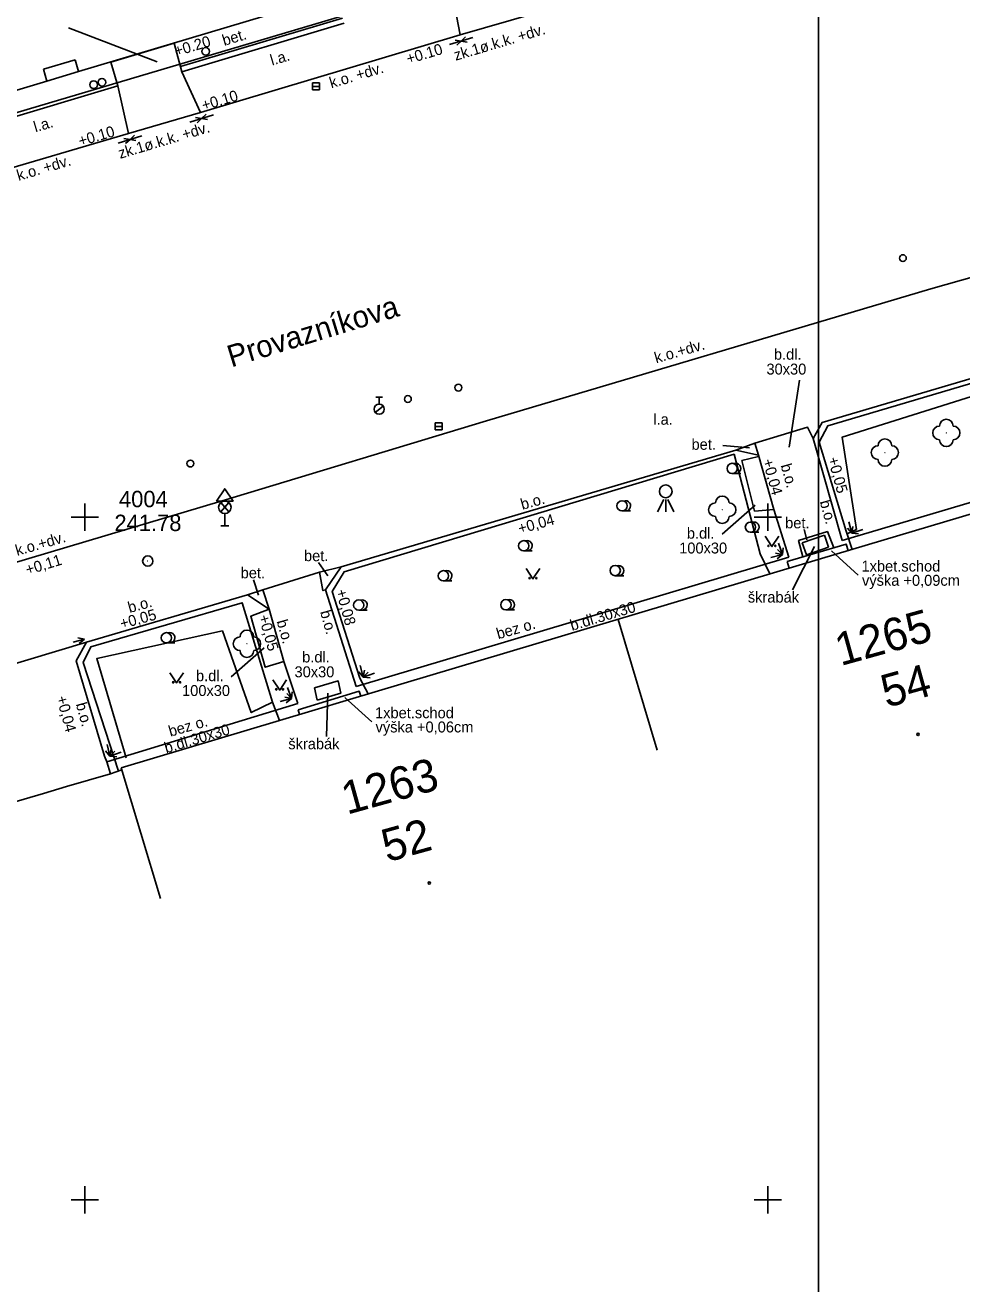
# Model space of a CAD drawing. Extents: x -597333 to -596488, y -1158921 to -1158644.
# Drawn here: x -596727.19 to -596692.9, y -1158753.07 to -1158706.99 of the extents above; entities that cross this region are included whole.
import ezdxf

# ---------------------------------------------------------------- set-up
doc = ezdxf.new("R2010")
doc.units = 0
for name, color, linetype in [('Vrstva 1', 7, 'Continuous'), ('Vrstva 11', 7, 'Continuous'), ('Vrstva 12', 7, 'Continuous'), ('Vrstva 14', 7, 'Continuous'), ('Vrstva 15', 7, 'Continuous'), ('Vrstva 2', 7, 'Continuous'), ('Vrstva 24', 7, 'Continuous'), ('Vrstva 25', 7, 'Continuous'), ('Vrstva 4', 7, 'Continuous'), ('Vrstva 42', 7, 'Continuous'), ('Vrstva 43', 7, 'Continuous'), ('Vrstva 44', 7, 'Continuous'), ('Vrstva 49', 7, 'Continuous'), ('Vrstva 5', 7, 'Continuous'), ('Vrstva 50', 7, 'Continuous'), ('Vrstva 62', 7, 'Continuous'), ('Vrstva 7', 7, 'Continuous'), ('Vrstva 9', 7, 'Continuous')]:
    doc.layers.add(name, color=color, linetype=linetype)

msp = doc.modelspace()

# ---------------------------------------------------------------- linework, layer by layer
at = {"layer": 'Vrstva 1'}
msp.add_lwpolyline([(-596908.148, -1158651.282), (-596908.148, -1158799.157), (-596698.148, -1158799.157), (-596698.148, -1158650.657), (-596905.25, -1158650.657)], dxfattribs=at)
msp.add_lwpolyline([(-596698.148, -1158650.657), (-596698.148, -1158799.157), (-596488.148, -1158799.157), (-596488.148, -1158650.657)], close=True, dxfattribs=at)
at = {"layer": 'Vrstva 11'}
for points in [[(-596684.09, -1158717.92), (-596697.28, -1158722.07), (-596696.76, -1158725.45), (-596697.07, -1158725.6)], [(-596718.13, -1158731.78), (-596718.91, -1158732.16), (-596719.97, -1158729.17), (-596724.57, -1158730.18), (-596723.49, -1158733.81)]]:
    msp.add_lwpolyline(points, dxfattribs=at)
at = {"layer": 'Vrstva 12'}
for p, q in [((-596724.07, -1158734.4), (-596723.65, -1158734.25)), ((-596726.52, -1158735.12), (-596725.68, -1158734.86))]:
    msp.add_line(p, q, dxfattribs=at)
at = {"layer": 'Vrstva 14'}
for p, q in [((-596701.31, -1158723.408), (-596700.998, -1158723.408)), ((-596705.34, -1158724.778), (-596705.027, -1158724.778)), ((-596700.64, -1158725.558), (-596700.328, -1158725.558)), ((-596708.94, -1158726.238), (-596708.628, -1158726.238)), ((-596711.88, -1158727.338), (-596711.568, -1158727.338)), ((-596705.59, -1158727.148), (-596705.277, -1158727.148)), ((-596714.98, -1158728.408), (-596714.667, -1158728.408)), ((-596709.59, -1158728.398), (-596709.277, -1158728.398)), ((-596722.02, -1158729.608), (-596721.708, -1158729.608))]:
    msp.add_line(p, q, dxfattribs=at)
for points in [[(-596700.104, -1158725.704), (-596699.854, -1158726.079), (-596699.604, -1158725.704)], [(-596708.85, -1158726.887), (-596708.6, -1158727.262), (-596708.35, -1158726.887)], [(-596721.894, -1158730.7), (-596721.644, -1158731.075), (-596721.394, -1158730.7)], [(-596718.122, -1158730.958), (-596717.872, -1158731.333), (-596717.622, -1158730.958)]]:
    msp.add_lwpolyline(points, dxfattribs=at)
for centre, radius in [((-596693.47, -1158721.92), 0.00025), ((-596695.72, -1158722.64), 0.00025), ((-596701.31, -1158723.22), 0.188), ((-596705.34, -1158724.59), 0.188), ((-596701.67, -1158724.73), 0.00025), ((-596700.64, -1158725.37), 0.188), ((-596708.94, -1158726.05), 0.188), ((-596699.979, -1158726.054), 0.025), ((-596699.729, -1158726.054), 0.025), ((-596705.59, -1158726.96), 0.188), ((-596711.88, -1158727.15), 0.188), ((-596708.725, -1158727.237), 0.025), ((-596708.475, -1158727.237), 0.025), ((-596714.98, -1158728.22), 0.188), ((-596709.59, -1158728.21), 0.188), ((-596722.02, -1158729.42), 0.188), ((-596719.07, -1158729.64), 0.00025), ((-596721.769, -1158731.05), 0.025), ((-596721.519, -1158731.05), 0.025), ((-596717.997, -1158731.308), 0.025), ((-596717.747, -1158731.308), 0.025)]:
    msp.add_circle(centre, radius, dxfattribs=at)
for centre, radius, start, end in [((-596693.72, -1158721.92), 0.25, 90, 270), ((-596693.47, -1158721.67), 0.25, 0, 180), ((-596693.22, -1158721.92), 0.25, 270, 90), ((-596695.72, -1158722.39), 0.25, 0, 180), ((-596693.47, -1158722.17), 0.25, 180, 360), ((-596695.97, -1158722.64), 0.25, 90, 270), ((-596695.47, -1158722.64), 0.25, 270, 90), ((-596701.185, -1158723.22), 0.188, 249.4944, 109.0474), ((-596695.72, -1158722.89), 0.25, 180, 360), ((-596705.215, -1158724.59), 0.188, 249.4944, 109.0474), ((-596701.92, -1158724.73), 0.25, 90, 270), ((-596701.67, -1158724.48), 0.25, 0, 180), ((-596701.42, -1158724.73), 0.25, 270, 90), ((-596701.67, -1158724.98), 0.25, 180, 360), ((-596700.515, -1158725.37), 0.188, 249.4944, 109.0474), ((-596708.815, -1158726.05), 0.188, 249.4944, 109.0474), ((-596705.465, -1158726.96), 0.188, 249.4944, 109.0474), ((-596711.755, -1158727.15), 0.188, 249.4944, 109.0474), ((-596714.855, -1158728.22), 0.188, 249.4944, 109.0474), ((-596709.465, -1158728.21), 0.188, 249.4944, 109.0474), ((-596721.895, -1158729.42), 0.188, 249.4944, 109.0474), ((-596719.07, -1158729.39), 0.25, 0, 180), ((-596719.32, -1158729.64), 0.25, 90, 270), ((-596718.82, -1158729.64), 0.25, 270, 90), ((-596719.07, -1158729.89), 0.25, 180, 360)]:
    msp.add_arc(centre, radius, start, end, dxfattribs=at)
at = {"layer": 'Vrstva 15'}
for centre in [(-596694.506, -1158732.959), (-596712.399, -1158738.402)]:
    msp.add_circle(centre, 0.0438, dxfattribs=at)
at = {"layer": 'Vrstva 2'}
for radius in [0.188, 0.00025]:
    msp.add_circle((-596722.7, -1158726.61), radius, dxfattribs=at)
at = {"layer": 'Vrstva 24'}
for p, q in [((-596714.377, -1158721.166), (-596714.082, -1158720.934)), ((-596714.355, -1158720.613), (-596714.105, -1158720.613)), ((-596714.23, -1158720.863), (-596714.23, -1158720.613))]:
    msp.add_line(p, q, dxfattribs=at)
for centre, radius in [((-596695.06, -1158715.52), 0.125), ((-596711.33, -1158720.26), 0.125), ((-596714.23, -1158721.05), 0.188), ((-596713.18, -1158720.68), 0.125), ((-596721.14, -1158723.04), 0.125)]:
    msp.add_circle(centre, radius, dxfattribs=at)
at = {"layer": 'Vrstva 25'}
for p, q in [((-596716.665, -1158709.23), (-596716.415, -1158709.23)), ((-596712.175, -1158721.68), (-596711.925, -1158721.68))]:
    msp.add_line(p, q, dxfattribs=at)
for points in [[(-596716.665, -1158709.355), (-596716.415, -1158709.355), (-596716.415, -1158709.105), (-596716.665, -1158709.105)], [(-596712.175, -1158721.806), (-596711.925, -1158721.806), (-596711.925, -1158721.555), (-596712.175, -1158721.555)]]:
    msp.add_lwpolyline(points, close=True, dxfattribs=at)
at = {"layer": 'Vrstva 4'}
for p, q in [((-596728.69, -1158710.54), (-596712.35, -1158705.69)), ((-596725.363, -1158708.26), (-596725.235, -1158708.692)), ((-596726.392, -1158709.037), (-596726.52, -1158708.605)), ((-596726.392, -1158709.037), (-596725.235, -1158708.692)), ((-596697.471, -1158726.348), (-596681.356, -1158721.53)), ((-596715.313, -1158731.682), (-596698.853, -1158726.761)), ((-596704.056, -1158733.535), (-596705.488, -1158728.745)), ((-596723.67, -1158734.18), (-596716.695, -1158732.095)), ((-596722.238, -1158738.971), (-596723.67, -1158734.18))]:
    msp.add_line(p, q, dxfattribs=at)
for points in [[(-596725.235, -1158708.692), (-596718.4, -1158706.652)], [(-596732.77, -1158710.94), (-596726.392, -1158709.037)], [(-596697.058, -1158726.224), (-596697.138, -1158725.988), (-596699.298, -1158726.628)], [(-596699.217, -1158726.87), (-596699.298, -1158726.628)], [(-596714.901, -1158731.558), (-596714.96, -1158731.38), (-596717.2, -1158732.06)], [(-596717.144, -1158732.229), (-596717.2, -1158732.06)]]:
    msp.add_lwpolyline(points, dxfattribs=at)
for centre in [(-596720.58, -1158707.95), (-596724.38, -1158709.08), (-596724.68, -1158709.17)]:
    msp.add_circle(centre, 0.14, dxfattribs=at)
at = {"layer": 'Vrstva 44'}
for p, q in [((-596719.73, -1158724.47), (-596720.03, -1158724.814)), ((-596720.03, -1158724.47), (-596719.73, -1158724.814)), ((-596703.814, -1158724.353), (-596704.04, -1158724.805)), ((-596703.74, -1158724.355), (-596703.74, -1158724.805)), ((-596703.665, -1158724.353), (-596703.44, -1158724.805)), ((-596719.88, -1158725.32), (-596719.88, -1158724.87)), ((-596720.03, -1158725.32), (-596719.73, -1158725.32))]:
    msp.add_line(p, q, dxfattribs=at)
msp.add_lwpolyline([(-596720.18, -1158724.414), (-596719.58, -1158724.414), (-596719.88, -1158723.964), (-596720.18, -1158724.414)], dxfattribs=at)
for centre, radius in [((-596703.74, -1158724.06), 0.234), ((-596719.88, -1158724.642), 0.228)]:
    msp.add_circle(centre, radius, dxfattribs=at)
at = {"layer": 'Vrstva 49'}
for p, q in [((-596725.601, -1158707.092), (-596722.361, -1158708.338)), ((-596710.798, -1158707.441), (-596711.66, -1158707.701)), ((-596711.229, -1158707.571), (-596711.449, -1158707.536)), ((-596711.229, -1158707.571), (-596711.393, -1158707.724)), ((-596711.229, -1158707.571), (-596711.067, -1158707.417)), ((-596711.229, -1158707.571), (-596711.011, -1158707.609)), ((-596720.3, -1158710.279), (-596721.162, -1158710.539)), ((-596720.731, -1158710.409), (-596720.569, -1158710.255)), ((-596720.731, -1158710.409), (-596720.951, -1158710.374)), ((-596720.731, -1158710.409), (-596720.895, -1158710.562)), ((-596720.731, -1158710.409), (-596720.513, -1158710.447)), ((-596722.92, -1158711.045), (-596723.782, -1158711.305)), ((-596723.351, -1158711.175), (-596723.571, -1158711.14)), ((-596723.351, -1158711.175), (-596723.515, -1158711.328)), ((-596723.351, -1158711.175), (-596723.189, -1158711.021)), ((-596723.351, -1158711.175), (-596723.133, -1158711.213)), ((-596698.841, -1158719.993), (-596699.229, -1158722.443)), ((-596701.655, -1158722.384), (-596700.669, -1158722.47)), ((-596701.681, -1158725.628), (-596700.473, -1158724.565)), ((-596698.677, -1158725.454), (-596698.572, -1158725.838)), ((-596697.093, -1158725.401), (-596696.935, -1158725.595)), ((-596696.888, -1158725.349), (-596696.935, -1158725.595)), ((-596696.755, -1158725.42), (-596696.935, -1158725.595)), ((-596696.686, -1158725.62), (-596696.935, -1158725.595)), ((-596699.718, -1158726.324), (-596699.473, -1158726.37)), ((-596699.666, -1158726.529), (-596699.473, -1158726.37)), ((-596699.647, -1158726.191), (-596699.473, -1158726.37)), ((-596699.447, -1158726.122), (-596699.473, -1158726.37)), ((-596716.448, -1158726.659), (-596716.106, -1158727.147)), ((-596718.831, -1158727.301), (-596718.647, -1158727.855)), ((-596725.259, -1158729.423), (-596725.014, -1158729.469)), ((-596725.207, -1158729.628), (-596725.014, -1158729.469)), ((-596719.647, -1158730.846), (-596718.44, -1158729.783)), ((-596714.767, -1158730.611), (-596714.814, -1158730.857)), ((-596714.972, -1158730.664), (-596714.814, -1158730.857)), ((-596714.634, -1158730.683), (-596714.814, -1158730.857)), ((-596714.565, -1158730.883), (-596714.814, -1158730.857)), ((-596717.613, -1158731.465), (-596717.439, -1158731.645)), ((-596717.413, -1158731.396), (-596717.439, -1158731.645)), ((-596717.684, -1158731.599), (-596717.439, -1158731.645)), ((-596717.632, -1158731.803), (-596717.439, -1158731.645)), ((-596724.243, -1158733.556), (-596724.085, -1158733.749)), ((-596724.039, -1158733.504), (-596724.085, -1158733.749)), ((-596723.906, -1158733.575), (-596724.085, -1158733.749)), ((-596723.836, -1158733.775), (-596724.085, -1158733.749))]:
    msp.add_line(p, q, dxfattribs=at)
for points in [[(-596697.042, -1158725.174), (-596696.935, -1158725.595)], [(-596696.525, -1158725.452), (-596696.935, -1158725.595)], [(-596699.615, -1158725.96), (-596699.473, -1158726.37)], [(-596699.893, -1158726.478), (-596699.473, -1158726.37)], [(-596698.299, -1158726.08), (-596699.098, -1158727.665)], [(-596697.677, -1158726.24), (-596696.699, -1158727.13)], [(-596725.434, -1158729.577), (-596725.014, -1158729.469)], [(-596714.921, -1158730.436), (-596714.814, -1158730.857)], [(-596714.404, -1158730.715), (-596714.814, -1158730.857)], [(-596717.581, -1158731.235), (-596717.439, -1158731.645)], [(-596716.105, -1158731.451), (-596716.156, -1158733.035)], [(-596717.859, -1158731.752), (-596717.439, -1158731.645)], [(-596715.483, -1158731.611), (-596714.505, -1158732.501)], [(-596724.192, -1158733.329), (-596724.085, -1158733.749)], [(-596723.675, -1158733.607), (-596724.085, -1158733.749)]]:
    msp.add_lwpolyline(points, dxfattribs=at)
at = {"layer": 'Vrstva 5'}
for p, q in [((-596721.737, -1158707.649), (-596724.047, -1158708.339)), ((-596726.52, -1158708.605), (-596725.363, -1158708.26)), ((-596697.14, -1158725.52), (-596696.919, -1158726.183)), ((-596700.29, -1158726.35), (-596699.93, -1158727.083)), ((-596697.471, -1158726.348), (-596698.853, -1158726.761)), ((-596714.629, -1158731.477), (-596714.94, -1158730.9)), ((-596718.13, -1158731.78), (-596717.878, -1158732.448)), ((-596715.313, -1158731.682), (-596716.695, -1158732.095)), ((-596725.68, -1158734.86), (-596724.07, -1158734.4)), ((-596730.15, -1158736.19), (-596726.52, -1158735.12))]:
    msp.add_line(p, q, dxfattribs=at)
at = {"layer": 'Vrstva 62'}
for p, q in [((-596725, -1158724.5), (-596725, -1158725.5)), ((-596700, -1158724.5), (-596700, -1158725.5)), ((-596725.5, -1158725), (-596724.5, -1158725)), ((-596700.5, -1158725), (-596699.5, -1158725)), ((-596725, -1158749.5), (-596725, -1158750.5)), ((-596700, -1158749.5), (-596700, -1158750.5)), ((-596725.5, -1158750), (-596724.5, -1158750)), ((-596700.5, -1158750), (-596699.5, -1158750))]:
    msp.add_line(p, q, dxfattribs=at)
at = {"layer": 'Vrstva 7'}
for p, q in [((-596711.57, -1158705.73), (-596711.27, -1158707.34)), ((-596721.503, -1158708.507), (-596715.567, -1158706.728)), ((-596721.45, -1158708.7), (-596715.51, -1158706.92)), ((-596721.45, -1158708.7), (-596721.737, -1158707.649)), ((-596723.8, -1158709.21), (-596724.047, -1158708.339)), ((-596720.77, -1158710.19), (-596721.45, -1158708.7)), ((-596729.41, -1158710.9), (-596723.8, -1158709.21)), ((-596723.8, -1158709.21), (-596723.4, -1158710.96)), ((-596697.28, -1158725.86), (-596681.932, -1158721.281)), ((-596698.75, -1158725.94), (-596697.93, -1158725.66)), ((-596698.59, -1158726.38), (-596698.75, -1158725.94)), ((-596697.93, -1158725.66), (-596697.78, -1158726.1)), ((-596715.07, -1158731.21), (-596699.24, -1158726.47)), ((-596697.78, -1158726.1), (-596698.59, -1158726.38)), ((-596734.01, -1158732.32), (-596724.94, -1158729.58)), ((-596724.2, -1158733.96), (-596717.21, -1158731.83))]:
    msp.add_line(p, q, dxfattribs=at)
for points in [[(-596731.26, -1158713.3), (-596728.72, -1158712.52), (-596723.4, -1158710.96), (-596720.77, -1158710.19), (-596711.27, -1158707.34), (-596708.51, -1158706.55), (-596699.59, -1158703.87), (-596697.63, -1158703.28), (-596692.1, -1158701.73), (-596684.68, -1158699.83)], [(-596719.98, -1158724.4), (-596710.3, -1158721.48), (-596694.04, -1158716.65), (-596687, -1158714.66), (-596677.59, -1158712.36), (-596674.94, -1158711.76), (-596672.4, -1158711.29)], [(-596697.28, -1158725.86), (-596698.35, -1158722.12), (-596698.02, -1158721.54), (-596683.88, -1158717.36), (-596682.94, -1158717.79), (-596682.77, -1158717.95)], [(-596700.48, -1158722.3), (-596698.55, -1158721.71), (-596698.35, -1158722.12)], [(-596701.17, -1158722.55), (-596700.48, -1158722.3), (-596700.34, -1158722.74)], [(-596715.07, -1158731.21), (-596716.19, -1158727.66), (-596715.62, -1158726.82), (-596701.17, -1158722.55), (-596700.34, -1158722.74), (-596699.78, -1158724.72), (-596699.24, -1158726.47)], [(-596700.34, -1158722.78), (-596700.95, -1158722.93), (-596700.49, -1158724.78), (-596699.78, -1158724.72)], [(-596782.84, -1158743.16), (-596770.71, -1158739.5), (-596748.23, -1158732.81), (-596734.11, -1158728.61), (-596733.99, -1158728.79), (-596728.47, -1158727.15), (-596728.46, -1158726.93), (-596719.98, -1158724.4)], [(-596698.728, -1158726.459), (-596698.88, -1158725.86), (-596697.82, -1158725.53), (-596697.589, -1158726.121)], [(-596716.42, -1158727.02), (-596715.62, -1158726.82)], [(-596719.05, -1158727.85), (-596718.49, -1158727.66), (-596716.42, -1158727.02)], [(-596716.19, -1158727.66), (-596716.29, -1158727.69), (-596716.42, -1158727.02)], [(-596724.07, -1158734.4), (-596724.2, -1158733.96), (-596724.29, -1158733.76), (-596725.32, -1158730.26), (-596724.94, -1158729.58), (-596719.05, -1158727.85), (-596718.26, -1158728.37), (-596717.72, -1158730.29), (-596717.21, -1158731.83)], [(-596718.49, -1158727.66), (-596718.26, -1158728.37), (-596718.93, -1158728.63), (-596718.4, -1158730.5), (-596717.72, -1158730.29)], [(-596716.6, -1158731.25), (-596715.73, -1158731), (-596715.63, -1158731.45)], [(-596716.6, -1158731.25), (-596716.5, -1158731.7)], [(-596716.5, -1158731.7), (-596715.63, -1158731.45)]]:
    msp.add_lwpolyline(points, dxfattribs=at)
at = {"layer": 'Vrstva 9'}
for points in [[(-596682.93, -1158721.1), (-596683.89, -1158717.54), (-596697.81, -1158721.66), (-596698.13, -1158722.26), (-596697.14, -1158725.52)], [(-596700.29, -1158726.35), (-596701.24, -1158722.7), (-596715.51, -1158727), (-596715.95, -1158727.72), (-596714.94, -1158730.9)], [(-596718.13, -1158731.78), (-596719.24, -1158728.14), (-596724.79, -1158729.75), (-596725.07, -1158730.32), (-596723.77, -1158734.3)]]:
    msp.add_lwpolyline(points, dxfattribs=at)

# ---------------------------------------------------------------- texts
at = {"layer": 'Vrstva 2'}
msp.add_text('4004', height=0.6, rotation=360, dxfattribs=at).set_placement((-596723.754, -1158724.64))
msp.add_text('241.78', height=0.6, dxfattribs=at).set_placement((-596723.922, -1158725.513))
at = {"layer": 'Vrstva 42'}
msp.add_text('Provazníkova', height=0.8, rotation=17, dxfattribs=at).set_placement((-596719.644, -1158719.524))
at = {"layer": 'Vrstva 43'}
for s, p in [('1265', (-596697.341, -1158730.459)), ('54', (-596695.662, -1158731.989)), ('1263', (-596715.409, -1158735.902)), ('52', (-596713.943, -1158737.645))]:
    msp.add_text(s, height=1.2, rotation=15.5254, dxfattribs=at).set_placement(p)
at = {"layer": 'Vrstva 49'}
for s, rotation, p in [('zk.1ø.k.k. +dv.', 16.6019, (-596711.429, -1158708.295)), ('bet.', 16.7312, (-596719.905, -1158707.75)), ('l.a.', 16.5505, (-596718.151, -1158708.473)), ('k.o. +dv.', 16.569, (-596715.984, -1158709.302)), ('l.a.', 16.5505, (-596726.812, -1158710.915)), ('zk.1ø.k.k. +dv.', 16.6019, (-596723.712, -1158711.886)), ('k.o. +dv.', 16.569, (-596727.429, -1158712.694)), ('k.o.+dv.', 16.0773, (-596704.09, -1158719.373)), ('b.o.', 285.7086, (-596699.54, -1158723.107)), ('b.o.', 15.3727, (-596708.991, -1158724.736)), ('b.o.', 285.3727, (-596698.109, -1158724.435)), ('k.o.+dv.', 16.0773, (-596727.481, -1158726.425)), ('b.o.', 15.3727, (-596723.367, -1158728.513)), ('b.dl.30x30', 16.6442, (-596707.173, -1158729.168)), ('b.o.', 285.7086, (-596717.988, -1158728.815)), ('b.o.', 285.3727, (-596716.396, -1158728.467)), ('bez o.', 15.9106, (-596709.874, -1158729.475)), ('b.o.', 285.3727, (-596725.338, -1158731.847)), ('bez o.', 15.9106, (-596721.874, -1158733.046)), ('b.dl.30x30', 16.6442, (-596722.027, -1158733.652))]:
    msp.add_text(s, height=0.4, rotation=rotation, dxfattribs=at).set_placement(p)
for s, p in [('b.dl.', (-596699.781, -1158719.239)), ('30x30', (-596700.054, -1158719.782)), ('l.a.', (-596704.195, -1158721.62)), ('bet.', (-596702.797, -1158722.537)), ('bet.', (-596699.37, -1158725.413)), ('b.dl.', (-596702.968, -1158725.791)), ('100x30', (-596703.249, -1158726.334)), ('bet.', (-596716.982, -1158726.615)), ('bet.', (-596719.3, -1158727.241)), ('1xbet.schod', (-596696.575, -1158726.995)), ('škrabák', (-596700.736, -1158728.13)), ('b.dl.', (-596717.049, -1158730.323)), ('b.dl.', (-596720.935, -1158731.009)), ('30x30', (-596717.329, -1158730.866)), ('100x30', (-596721.445, -1158731.552)), ('1xbet.schod', (-596714.381, -1158732.366)), ('škrabák', (-596717.556, -1158733.501))]:
    msp.add_text(s, height=0.4, dxfattribs=at).set_placement(p)
at = {"layer": 'Vrstva 50'}
for s, rotation, p in [('+0.20', 16.6815, (-596721.661, -1158708.138)), ('+0.10', 16.5655, (-596713.169, -1158708.421)), ('+0.10', 16.5655, (-596720.657, -1158710.125)), ('+0.10', 16.5655, (-596725.173, -1158711.434)), ('+0,04', 285.7086, (-596700.204, -1158722.93)), ('+0,05', 285.3727, (-596697.813, -1158722.859)), ('+0,04', 15.3727, (-596709.085, -1158725.62)), ('+0,11', 16.8584, (-596727.106, -1158727.128)), ('+0,08', 285.3727, (-596715.82, -1158727.699)), ('+0,05', 15.3727, (-596723.657, -1158729.101)), ('+0,05', 285.7086, (-596718.652, -1158728.637)), ('+0,04', 285.3727, (-596726.053, -1158731.604))]:
    msp.add_text(s, height=0.4, rotation=rotation, dxfattribs=at).set_placement(p)
for s, p in [('výška +0,09cm', (-596696.556, -1158727.516)), ('výška +0,06cm', (-596714.362, -1158732.886))]:
    msp.add_text(s, height=0.4, dxfattribs=at).set_placement(p)

doc.saveas('drawing.dxf')
